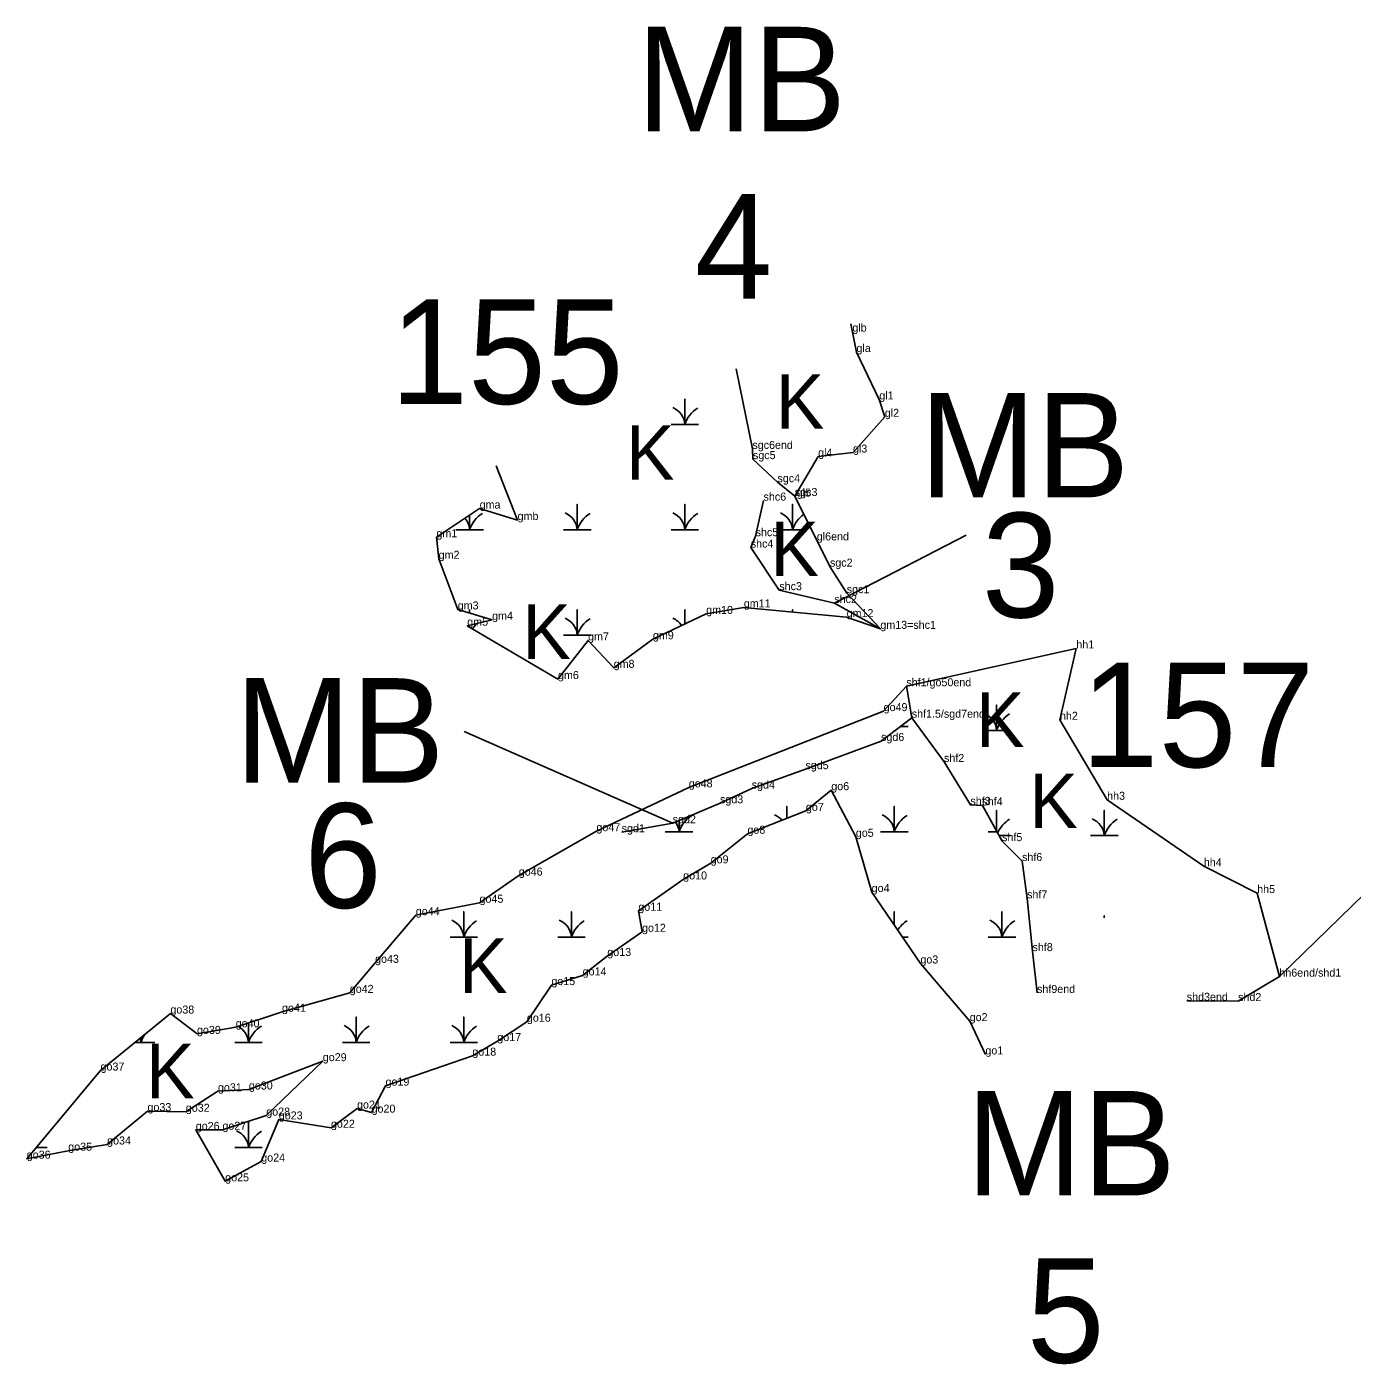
# Model space of a CAD drawing. Extents: x 2072529 to 2268796, y 436423 to 470406.
# Drawn here: x 2177497 to 2178325, y 450116 to 450952 of the extents above; entities that cross this region are included whole.
import ezdxf

# ---------------------------------------------------------------- set-up
doc = ezdxf.new("R2010")
doc.units = 0
for name, color, linetype in [('Default', 7, 'Continuous'), ('Exist Environmental Wetland Boundary', 7, 'Continuous'), ('Exist Environmental Wetland Boundary Cogo Comment', 7, 'Continuous'), ('Exist Hydro Jurisdictional Stream or Body of Water NEU Mitigable', 7, 'Continuous'), ('Exist Hydro Jurisdictional Stream or Body of Water NEU Mitigable Cogo Comment', 7, 'Continuous'), ('Exist Hydro Swamp or Marsh', 7, 'Continuous'), ('Old_Level_20', 7, 'Continuous')]:
    doc.layers.add(name, color=color, linetype=linetype)

msp = doc.modelspace()

# ---------------------------------------------------------------- linework, layer by layer
at = {"layer": 'Default'}
for p, q in [((2178083.48, 450634.25), (2178001.13, 450591.78)), ((2177769.92, 450511.55), (2177900.13, 450454.2))]:
    msp.add_line(p, q, dxfattribs=at)
at = {"layer": 'Exist Environmental Wetland Boundary'}
for points in [[(2177976.45, 450658.67), (2177991.04, 450683.33), (2178012.8, 450685.83), (2178032.67, 450708.15), (2178029.21, 450718.98), (2178014.96, 450748.63), (2178011.42, 450766.34)], [(2177789.84, 450677.43), (2177803.23, 450643.67), (2177779.52, 450650.82), (2177752.49, 450632.86), (2177753.91, 450619.45), (2177765.83, 450587.79), (2177787.28, 450581.35), (2177771.76, 450577.61), (2177828.46, 450544.3), (2177847.25, 450568.44), (2177863.26, 450551.29), (2177887.79, 450569.14), (2177921.06, 450585.01), (2177944.57, 450589.07), (2178008.82, 450583.02), (2178029.88, 450575.67), (2178008.89, 450597.94)], [(2178152.32, 450563.41), (2178046.13, 450539.79), (2178031.93, 450524.26), (2177910.17, 450476.58), (2177852.47, 450449.22), (2177803.96, 450421.48), (2177779.44, 450404.5), (2177739.59, 450396.71), (2177714.17, 450366.96), (2177698.36, 450348.2), (2177656.02, 450336.38), (2177627.09, 450326.68), (2177602.91, 450322.54), (2177586.29, 450335.27), (2177542.65, 450299.66), (2177496.53, 450244.59), (2177522.46, 450249.59), (2177546.74, 450253.45), (2177571.98, 450274.3), (2177595.92, 450273.9), (2177616.02, 450286.67), (2177635.34, 450287.8), (2177681.5, 450305.52), (2177646.19, 450271.5), (2177618.8, 450262.69), (2177602.14, 450262.54), (2177620.52, 450230.44), (2177643.06, 450242.79), (2177654.01, 450269.12), (2177686.64, 450263.91), (2177702.91, 450275.9), (2177712, 450273.37), (2177720.72, 450290.19), (2177774.96, 450308.94), (2177790.56, 450318.06), (2177809.03, 450330.17), (2177824.33, 450353.05), (2177843.87, 450359.1), (2177859.29, 450371.23), (2177880.99, 450386.36), (2177878.67, 450399.47), (2177906.7, 450419.08), (2177923.87, 450429.15), (2177946.83, 450447.62), (2177983.37, 450461.87), (2177999.22, 450474.85), (2178014.56, 450445.73), (2178024.46, 450411.19), (2178054.91, 450366.56), (2178085.72, 450330.52), (2178095.52, 450309.72)], [(2178152.32, 450563.41), (2178142.1, 450518.83), (2178171.59, 450468.85), (2178232, 450427.35), (2178265.34, 450410.56), (2178279.19, 450358.33)]]:
    msp.add_lwpolyline(points, dxfattribs=at)
at = {"layer": 'Exist Hydro Jurisdictional Stream or Body of Water NEU Mitigable'}
for points in [[(2177939.71, 450738.05), (2177949.93, 450688.08), (2177950.3, 450681.71), (2177965.6, 450667.29), (2177976.45, 450658.67), (2177998.39, 450614.54), (2178008.89, 450597.94)], [(2177956.89, 450655.78), (2177951.96, 450633.56), (2177948.91, 450626.43), (2177966.76, 450599.83), (2178001.13, 450591.78), (2178029.88, 450575.67)], [(2178046.13, 450539.79), (2178049.51, 450520.15), (2178069.65, 450492.48), (2178086.16, 450465.65), (2178093.62, 450465.31), (2178105.96, 450443), (2178118.41, 450430.57), (2178121.56, 450407.23), (2178124.96, 450374.29), (2178127.8, 450348.15)], [(2177868.26, 450448.57), (2177900.13, 450454.2), (2177929.69, 450466.66), (2177949.48, 450475.82), (2177983.08, 450487.96), (2178030.31, 450505.58), (2178049.51, 450520.15)], [(2178221.35, 450343.23), (2178253.43, 450343.09), (2178279.19, 450358.33), (2178332.13, 450409.94)]]:
    msp.add_lwpolyline(points, dxfattribs=at)
at = {"layer": 'Exist Hydro Swamp or Marsh'}
for points in [[(2177899.14, 450703.41), (2177907.74, 450703.41), (2177907.74, 450719.19), (2177907.74, 450703.41), (2177916.34, 450703.41)], [(2177764.64, 450637.61), (2177773.24, 450637.61), (2177773.24, 450646.64)], [(2177773.24, 450646.64), (2177773.24, 450637.61), (2177781.84, 450637.61)], [(2177831.89, 450637.61), (2177840.49, 450637.61), (2177840.49, 450653.39), (2177840.49, 450637.61), (2177849.09, 450637.61)], [(2177899.14, 450637.61), (2177907.74, 450637.61), (2177907.74, 450653.39), (2177907.74, 450637.61), (2177916.34, 450637.61)], [(2177966.39, 450637.61), (2177974.99, 450637.61), (2177974.99, 450653.39), (2177974.99, 450637.61), (2177983.59, 450637.61)], [(2177773.24, 450585.56), (2177773.24, 450587.59), (2177773.24, 450585.56)], [(2177831.89, 450571.81), (2177840.49, 450571.81), (2177840.49, 450587.59), (2177840.49, 450571.81), (2177849.09, 450571.81)], [(2177907.74, 450578.66), (2177907.74, 450587.59), (2177907.74, 450578.66)], [(2177974.99, 450586.21), (2177974.99, 450587.59), (2177974.99, 450586.21)], [(2177773.24, 450576.74), (2177773.24, 450577.97)], [(2177773.24, 450577.97), (2177773.24, 450576.74)], [(2177781.64, 450571.81), (2177781.84, 450571.81)], [(2178093.94, 450512.24), (2178102.54, 450512.24), (2178102.54, 450528.02), (2178102.54, 450512.24), (2178111.14, 450512.24)], [(2178042.3, 450514.67), (2178047.21, 450514.67)], [(2177971.36, 450457.19), (2177971.36, 450464.66), (2177971.36, 450457.19)], [(2178030.01, 450448.87), (2178038.61, 450448.87), (2178038.61, 450464.66), (2178038.61, 450448.87), (2178047.21, 450448.87)], [(2178102.54, 450449.19), (2178102.54, 450462.22), (2178102.54, 450449.19)], [(2178161.19, 450446.44), (2178169.79, 450446.44), (2178169.79, 450462.22), (2178169.79, 450446.44), (2178178.39, 450446.44)], [(2177895.51, 450448.87), (2177904.11, 450448.87), (2177904.11, 450455.88)], [(2177904.11, 450455.88), (2177904.11, 450448.87), (2177912.71, 450448.87)], [(2178097.26, 450448.87), (2178102.71, 450448.87)], [(2178104.06, 450446.44), (2178111.14, 450446.44)], [(2177761.01, 450383.07), (2177769.61, 450383.07), (2177769.61, 450398.86), (2177769.61, 450383.07), (2177778.21, 450383.07)], [(2177828.26, 450383.07), (2177836.86, 450383.07), (2177836.86, 450398.86), (2177836.86, 450383.07), (2177845.46, 450383.07)], [(2178038.61, 450390.45), (2178038.61, 450398.86), (2178038.61, 450390.45)], [(2178097.26, 450383.07), (2178105.86, 450383.07), (2178105.86, 450398.86), (2178105.86, 450383.07), (2178114.46, 450383.07)], [(2178169.79, 450395.16), (2178169.79, 450396.42), (2178169.79, 450395.16)], [(2178043.64, 450383.07), (2178047.21, 450383.07)], [(2177626.51, 450317.27), (2177635.11, 450317.27), (2177635.11, 450329.37)], [(2177635.11, 450329.37), (2177635.11, 450317.27), (2177643.71, 450317.27)], [(2177693.76, 450317.27), (2177702.36, 450317.27), (2177702.36, 450333.06), (2177702.36, 450317.27), (2177710.96, 450317.27)], [(2177761.01, 450317.27), (2177769.61, 450317.27), (2177769.61, 450333.06), (2177769.61, 450317.27), (2177778.21, 450317.27)], [(2177564.24, 450317.27), (2177567.86, 450317.27), (2177567.86, 450320.23)], [(2177567.86, 450320.23), (2177567.86, 450317.27), (2177576.46, 450317.27)], [(2177626.51, 450251.47), (2177635.11, 450251.47), (2177635.11, 450267.26), (2177635.11, 450251.47), (2177643.71, 450251.47)], [(2177502.3, 450251.47), (2177509.21, 450251.47)]]:
    msp.add_lwpolyline(points, dxfattribs=at)
for centre, radius, start, end in [((2177895.47, 450702.52), 12.3, 4.14034, 67.53497), ((2177925.98, 450697.34), 19.22, 122.12745, 161.62219), ((2177791.48, 450631.54), 19.22, 122.12745, 161.62219), ((2177828.22, 450636.72), 12.3, 4.14034, 67.53497), ((2177858.73, 450631.54), 19.22, 122.12745, 161.62219), ((2177895.47, 450636.72), 12.3, 4.14034, 67.53497), ((2177925.98, 450631.54), 19.22, 122.12745, 161.62219), ((2177962.72, 450636.72), 12.3, 4.14034, 67.53497), ((2177993.23, 450631.54), 19.22, 125.25512, 161.62219), ((2177760.97, 450636.72), 12.3, 4.14034, 40.51361), ((2177791.48, 450565.74), 19.22, 136.34183, 148.84619), ((2177828.22, 450570.92), 12.3, 4.14034, 67.53497), ((2177858.73, 450565.74), 19.22, 122.12745, 161.62219), ((2177895.47, 450570.92), 12.3, 33.47003, 67.53497), ((2178090.27, 450511.35), 12.3, 4.14034, 67.53497), ((2178120.78, 450506.18), 19.22, 122.12745, 161.62219), ((2177891.84, 450447.99), 12.3, 4.14034, 34.62945), ((2177922.35, 450442.81), 19.22, 122.12745, 161.62219), ((2177959.09, 450447.99), 12.3, 40.85078, 67.53497), ((2178026.34, 450447.99), 12.3, 4.14034, 67.53497), ((2178056.85, 450442.81), 19.22, 122.12745, 161.62219), ((2178120.78, 450440.38), 19.22, 122.12745, 156.43098), ((2178157.52, 450445.55), 12.3, 4.14034, 67.53497), ((2178188.03, 450440.38), 19.22, 122.12745, 161.62219), ((2177757.34, 450382.19), 12.3, 4.14034, 67.53497), ((2177787.85, 450377.01), 19.22, 122.12745, 161.62219), ((2177824.59, 450382.19), 12.3, 4.14034, 67.53497), ((2177855.1, 450377.01), 19.22, 122.12745, 161.62219), ((2178056.85, 450377.01), 19.22, 122.12745, 147.26178), ((2178093.59, 450382.19), 12.3, 4.14034, 67.53497), ((2178124.1, 450377.01), 19.22, 122.12745, 161.62219), ((2177690.09, 450316.39), 12.3, 4.14034, 67.53497), ((2177757.34, 450316.39), 12.3, 4.14034, 67.53497), ((2177555.59, 450316.39), 12.3, 4.14034, 16.34926), ((2177586.1, 450311.21), 19.22, 144.78316, 161.62219), ((2177622.84, 450316.39), 12.3, 4.14034, 61.68812), ((2177653.35, 450311.21), 19.22, 122.12745, 161.62219), ((2177720.6, 450311.21), 19.22, 122.12745, 161.62219), ((2177787.85, 450311.21), 19.22, 122.12745, 161.62219), ((2177622.84, 450250.59), 12.3, 4.14034, 67.53497), ((2177653.35, 450245.41), 19.22, 122.12745, 161.62219)]:
    msp.add_arc(centre, radius, start, end, dxfattribs=at)
at = {"layer": 'Old_Level_20'}
for p, q in [((2178012.41, 450761.38), (2178012.41, 450761.38)), ((2178014.96, 450748.63), (2178014.96, 450748.63)), ((2178029.21, 450718.98), (2178029.21, 450718.98)), ((2178032.67, 450708.15), (2178032.67, 450708.15)), ((2177949.93, 450688.08), (2177949.93, 450688.08)), ((2177950.3, 450681.71), (2177950.3, 450681.71)), ((2177991.04, 450683.33), (2177991.04, 450683.33)), ((2178012.8, 450685.83), (2178012.8, 450685.83)), ((2177965.6, 450667.29), (2177965.6, 450667.29)), ((2177956.89, 450655.78), (2177956.89, 450655.78)), ((2177976.45, 450658.67), (2177976.45, 450658.67)), ((2177977.65, 450658.34), (2177977.65, 450658.34)), ((2177779.52, 450650.82), (2177779.52, 450650.82)), ((2177803.23, 450643.67), (2177803.23, 450643.67)), ((2177752.49, 450632.86), (2177752.49, 450632.86)), ((2177951.96, 450633.56), (2177951.96, 450633.56)), ((2177990.16, 450630.93), (2177990.16, 450630.93)), ((2177948.91, 450626.43), (2177948.91, 450626.43)), ((2177753.91, 450619.45), (2177753.91, 450619.45)), ((2177998.39, 450614.54), (2177998.39, 450614.54)), ((2177966.76, 450599.83), (2177966.76, 450599.83)), ((2178008.89, 450597.94), (2178008.89, 450597.94)), ((2177765.83, 450587.79), (2177765.83, 450587.79)), ((2177944.57, 450589.07), (2177944.57, 450589.07)), ((2178001.13, 450591.78), (2178001.13, 450591.78)), ((2177787.28, 450581.35), (2177787.28, 450581.35)), ((2177921.06, 450585.01), (2177921.06, 450585.01)), ((2178008.82, 450583.02), (2178008.82, 450583.02)), ((2177771.76, 450577.61), (2177771.76, 450577.61)), ((2178029.88, 450575.67), (2178029.88, 450575.67)), ((2178029.88, 450575.67), (2178029.88, 450575.67)), ((2177847.25, 450568.44), (2177847.25, 450568.44)), ((2177887.79, 450569.14), (2177887.79, 450569.14)), ((2178152.32, 450563.41), (2178152.32, 450563.41)), ((2177863.26, 450551.29), (2177863.26, 450551.29)), ((2177828.46, 450544.3), (2177828.46, 450544.3)), ((2178046.13, 450539.79), (2178046.13, 450539.79)), ((2178046.13, 450539.79), (2178046.13, 450539.79)), ((2178031.93, 450524.26), (2178031.93, 450524.26)), ((2178049.51, 450520.15), (2178049.51, 450520.15)), ((2178142.1, 450518.83), (2178142.1, 450518.83)), ((2178030.31, 450505.58), (2178030.31, 450505.58)), ((2177983.08, 450487.96), (2177983.08, 450487.96)), ((2178069.65, 450492.48), (2178069.65, 450492.48)), ((2177910.17, 450476.58), (2177910.17, 450476.58)), ((2177949.48, 450475.82), (2177949.48, 450475.82)), ((2177999.22, 450474.85), (2177999.22, 450474.85)), ((2177929.69, 450466.66), (2177929.69, 450466.66)), ((2177983.37, 450461.87), (2177983.37, 450461.87)), ((2178086.16, 450465.65), (2178086.16, 450465.65)), ((2178093.62, 450465.31), (2178093.62, 450465.31)), ((2178171.59, 450468.85), (2178171.59, 450468.85)), ((2177900.13, 450454.2), (2177900.13, 450454.2)), ((2177852.47, 450449.22), (2177852.47, 450449.22)), ((2177868.26, 450448.57), (2177868.26, 450448.57)), ((2177946.83, 450447.62), (2177946.83, 450447.62)), ((2178014.56, 450445.73), (2178014.56, 450445.73)), ((2178105.96, 450443), (2178105.96, 450443)), ((2177923.87, 450429.15), (2177923.87, 450429.15)), ((2178118.41, 450430.57), (2178118.41, 450430.57)), ((2177803.96, 450421.48), (2177803.96, 450421.48)), ((2178232, 450427.35), (2178232, 450427.35)), ((2177906.7, 450419.08), (2177906.7, 450419.08)), ((2177779.44, 450404.5), (2177779.44, 450404.5)), ((2178024.46, 450411.19), (2178024.46, 450411.19)), ((2178121.56, 450407.23), (2178121.56, 450407.23)), ((2178265.34, 450410.56), (2178265.34, 450410.56)), ((2177739.59, 450396.71), (2177739.59, 450396.71)), ((2177878.67, 450399.47), (2177878.67, 450399.47)), ((2177880.99, 450386.36), (2177880.99, 450386.36)), ((2177859.29, 450371.23), (2177859.29, 450371.23)), ((2178124.96, 450374.29), (2178124.96, 450374.29)), ((2177714.17, 450366.96), (2177714.17, 450366.96)), ((2178054.91, 450366.56), (2178054.91, 450366.56)), ((2177824.33, 450353.05), (2177824.33, 450353.05)), ((2177843.87, 450359.1), (2177843.87, 450359.1)), ((2178279.19, 450358.33), (2178279.19, 450358.33)), ((2178279.19, 450358.33), (2178279.19, 450358.33)), ((2177698.36, 450348.2), (2177698.36, 450348.2)), ((2178127.8, 450348.15), (2178127.8, 450348.15)), ((2177656.02, 450336.38), (2177656.02, 450336.38)), ((2178221.35, 450343.23), (2178221.35, 450343.23)), ((2178253.43, 450343.09), (2178253.43, 450343.09)), ((2177586.29, 450335.27), (2177586.29, 450335.27)), ((2177809.03, 450330.17), (2177809.03, 450330.17)), ((2178085.72, 450330.52), (2178085.72, 450330.52)), ((2177602.91, 450322.54), (2177602.91, 450322.54)), ((2177627.09, 450326.68), (2177627.09, 450326.68)), ((2177790.56, 450318.06), (2177790.56, 450318.06)), ((2177681.5, 450305.52), (2177681.5, 450305.52)), ((2177774.96, 450308.94), (2177774.96, 450308.94)), ((2178095.52, 450309.72), (2178095.52, 450309.72)), ((2177542.65, 450299.66), (2177542.65, 450299.66)), ((2177616.02, 450286.67), (2177616.02, 450286.67)), ((2177635.34, 450287.8), (2177635.34, 450287.8)), ((2177720.72, 450290.19), (2177720.72, 450290.19)), ((2177571.98, 450274.3), (2177571.98, 450274.3)), ((2177595.92, 450273.9), (2177595.92, 450273.9)), ((2177646.19, 450271.5), (2177646.19, 450271.5)), ((2177702.91, 450275.9), (2177702.91, 450275.9)), ((2177712, 450273.37), (2177712, 450273.37)), ((2177602.14, 450262.54), (2177602.14, 450262.54)), ((2177618.8, 450262.69), (2177618.8, 450262.69)), ((2177654.01, 450269.12), (2177654.01, 450269.12)), ((2177686.64, 450263.91), (2177686.64, 450263.91)), ((2177546.74, 450253.45), (2177546.74, 450253.45)), ((2177496.53, 450244.59), (2177496.53, 450244.59)), ((2177522.46, 450249.59), (2177522.46, 450249.59)), ((2177643.06, 450242.79), (2177643.06, 450242.79)), ((2177620.52, 450230.44), (2177620.52, 450230.44))]:
    msp.add_line(p, q, dxfattribs=at)

# ---------------------------------------------------------------- texts
at = {"layer": 'Default'}
for s, p in [('MB', (2177877.48, 450886.56)), ('4', (2177913.89, 450782.01)), ('155', (2177723.71, 450716.24)), ('MB', (2178054.37, 450657.74)), ('3', (2178093.27, 450582.81)), ('157', (2178155.18, 450489.24)), ('MB', (2177626.51, 450479.52)), ('6', (2177669.82, 450401.3)), ('MB', (2178083.42, 450221.6)), ('5', (2178121.38, 450117.06))]:
    msp.add_text(s, height=65.34, dxfattribs=at).set_placement(p)
at = {"layer": 'Exist Environmental Wetland Boundary Cogo Comment'}
for s, p in [('glb', (2178012.41, 450761.38)), ('gla', (2178014.96, 450748.63)), ('gl1', (2178029.21, 450718.98)), ('gl2', (2178032.67, 450708.15)), ('gl4', (2177991.04, 450683.33)), ('gl3', (2178012.8, 450685.83)), ('gma', (2177779.52, 450650.82)), ('gmb', (2177803.23, 450643.67)), ('gm1', (2177752.49, 450632.86)), ('gm2', (2177753.91, 450619.45)), ('gm3', (2177765.83, 450587.79)), ('gm10', (2177921.06, 450585.01)), ('gm11', (2177944.57, 450589.07)), ('gm5', (2177771.76, 450577.61)), ('gm4', (2177787.28, 450581.35)), ('gm7', (2177847.25, 450568.44)), ('gm9', (2177887.79, 450569.14)), ('hh1', (2178152.32, 450563.41)), ('gm8', (2177863.26, 450551.29)), ('gm6', (2177828.46, 450544.3)), ('hh2', (2178142.1, 450518.83)), ('go48', (2177910.17, 450476.58)), ('go6', (2177999.22, 450474.85)), ('hh3', (2178171.59, 450468.85)), ('go7', (2177983.37, 450461.87)), ('go47', (2177852.47, 450449.22)), ('go8', (2177946.83, 450447.62)), ('go5', (2178014.56, 450445.73)), ('go9', (2177923.87, 450429.15)), ('hh4', (2178232, 450427.35)), ('go46', (2177803.96, 450421.48)), ('go10', (2177906.7, 450419.08)), ('go4', (2178024.46, 450411.19)), ('hh5', (2178265.34, 450410.56)), ('go45', (2177779.44, 450404.5)), ('go11', (2177878.67, 450399.47)), ('go44', (2177739.59, 450396.71)), ('go12', (2177880.99, 450386.36)), ('go43', (2177714.17, 450366.96)), ('go13', (2177859.29, 450371.23)), ('go3', (2178054.91, 450366.56)), ('go14', (2177843.87, 450359.1)), ('hh6end/shd1', (2178279.19, 450358.33)), ('go42', (2177698.36, 450348.2)), ('go15', (2177824.33, 450353.05)), ('go38', (2177586.29, 450335.27)), ('go41', (2177656.02, 450336.38)), ('go40', (2177627.09, 450326.68)), ('go16', (2177809.03, 450330.17)), ('go2', (2178085.72, 450330.52)), ('go39', (2177602.91, 450322.54)), ('go17', (2177790.56, 450318.06)), ('go18', (2177774.96, 450308.94)), ('go1', (2178095.52, 450309.72)), ('go37', (2177542.65, 450299.66)), ('go29', (2177681.5, 450305.52)), ('go19', (2177720.72, 450290.19)), ('go31', (2177616.02, 450286.67)), ('go30', (2177635.34, 450287.8)), ('go33', (2177571.98, 450274.3)), ('go32', (2177595.92, 450273.9)), ('go21', (2177702.91, 450275.9)), ('go20', (2177712, 450273.37)), ('go28', (2177646.19, 450271.5)), ('go23', (2177654.01, 450269.12)), ('go26', (2177602.14, 450262.54)), ('go27', (2177618.8, 450262.69)), ('go22', (2177686.64, 450263.91)), ('go35', (2177522.46, 450249.59)), ('go34', (2177546.74, 450253.45)), ('go36', (2177496.53, 450244.59)), ('go24', (2177643.06, 450242.79)), ('go25', (2177620.52, 450230.44))]:
    msp.add_text(s, height=5, dxfattribs=at).set_placement(p)
at = {"layer": 'Exist Hydro Jurisdictional Stream or Body of Water NEU Mitigable Cogo Comment'}
for s, p in [('sgc6end', (2177949.93, 450688.08)), ('sgc5', (2177950.3, 450681.71)), ('sgc4', (2177965.6, 450667.29)), ('sgc3', (2177976.45, 450658.67)), ('gl5', (2177977.65, 450658.34)), ('shc6', (2177956.89, 450655.78)), ('shc5', (2177951.96, 450633.56)), ('shc4', (2177948.91, 450626.43)), ('gl6end', (2177990.16, 450630.93)), ('sgc2', (2177998.39, 450614.54)), ('shc3', (2177966.76, 450599.83)), ('shc2', (2178001.13, 450591.78)), ('sgc1', (2178008.89, 450597.94)), ('gm12', (2178008.82, 450583.02)), ('gm13=shc1', (2178029.88, 450575.67)), ('shf1/go50end', (2178046.13, 450539.79)), ('shf1', (2178046.13, 450539.79)), ('go49', (2178031.93, 450524.26)), ('shf1.5/sgd7end', (2178049.51, 450520.15)), ('sgd6', (2178030.31, 450505.58)), ('shf2', (2178069.65, 450492.48)), ('sgd5', (2177983.08, 450487.96)), ('sgd4', (2177949.48, 450475.82)), ('sgd3', (2177929.69, 450466.66)), ('shf3', (2178086.16, 450465.65)), ('shf4', (2178093.62, 450465.31)), ('sgd1', (2177868.26, 450448.57)), ('sgd2', (2177900.13, 450454.2)), ('shf5', (2178105.96, 450443)), ('shf6', (2178118.41, 450430.57)), ('shf7', (2178121.56, 450407.23)), ('shf8', (2178124.96, 450374.29)), ('shf9end', (2178127.8, 450348.15)), ('shd3end', (2178221.35, 450343.23)), ('shd2', (2178253.43, 450343.09))]:
    msp.add_text(s, height=5, dxfattribs=at).set_placement(p)
at = {"layer": 'Exist Hydro Swamp or Marsh'}
for p in [(2177964.52, 450700.75), (2177870.97, 450668.79), (2177961.23, 450608.61), (2177806.1, 450556.9), (2178089.57, 450501.9), (2178122.95, 450451.13), (2177766.61, 450348.18), (2177571.05, 450282.36)]:
    msp.add_text('K', height=34, dxfattribs=at).set_placement(p)

doc.saveas('drawing.dxf')
